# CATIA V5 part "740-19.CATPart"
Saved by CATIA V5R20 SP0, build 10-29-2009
Part number: 740-19
Bounding box of the stored display mesh (mm): x -19.9 to 19.9, y -18 to 19.9, z -23 to 12
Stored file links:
  C:\Users\Utente\Desktop\IO LAVORO\3D X SITO CF\X SITO\740\740-19.CATPart
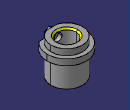
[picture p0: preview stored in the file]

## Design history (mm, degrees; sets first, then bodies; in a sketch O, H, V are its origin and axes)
Set1
  DatumSurface1 to DatumSurface35 "740-19"
Body1 (main body)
